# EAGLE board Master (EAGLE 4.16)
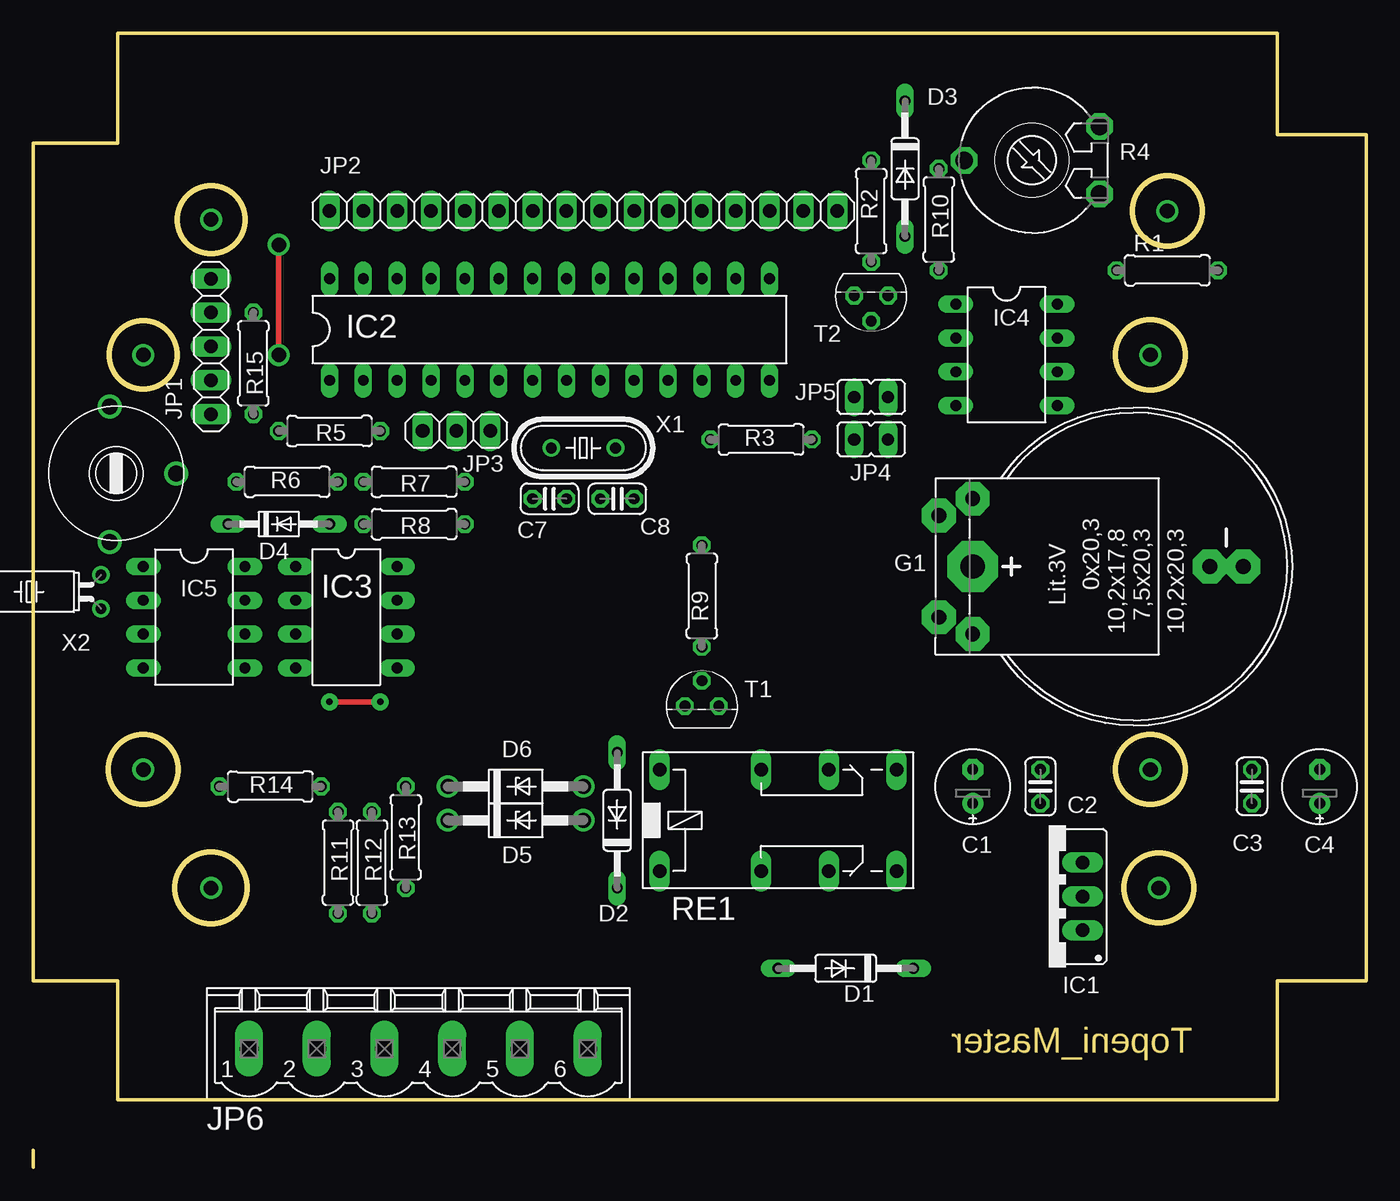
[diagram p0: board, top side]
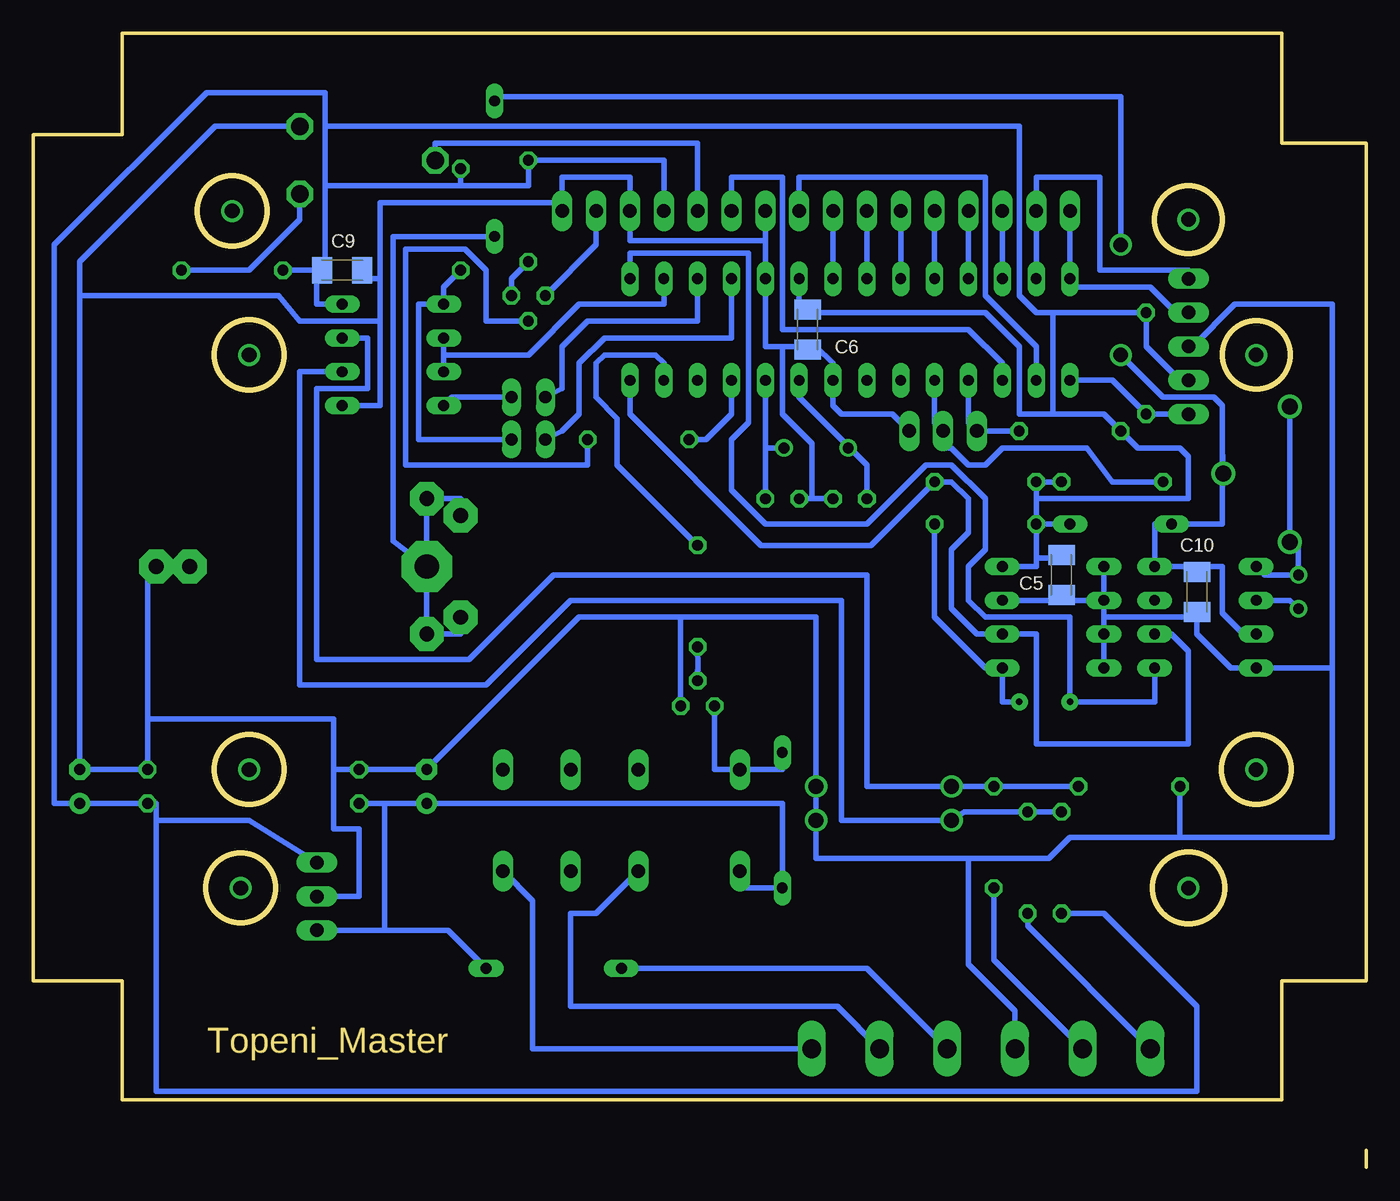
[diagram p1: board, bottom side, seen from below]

Size 100.01 x 85.09 mm. Coordinates in mm from the lower left corner, seen from the top.
Outline: 77 segments
Outline: circle at 13.34,71.12 radius 2.54
Outline: circle at 8.26,60.96 radius 2.54
Outline: circle at 8.26,29.84 radius 2.62
Outline: circle at 13.34,20.95 radius 2.69
Outline: circle at 85.09,71.75 radius 2.62
Outline: circle at 83.82,60.96 radius 2.62
Outline: circle at 83.82,29.84 radius 2.62
Outline: circle at 84.45,20.95 radius 2.62
Copper layers (1*16): Top 0.035mm / dielectric 1.5mm / Bottom 0.035mm
Design rules "default": minimum track width 10mil, minimum drill 19mil, track to track 8mil, track to pad 8mil, pad to pad 8mil, via to via 8mil, smd to smd 8mil, copper to edge 40mil, drill to drill 8mil, minimum pad ring 10mil, minimum via ring 8mil, stop-mask expansion 4mil, vias tented up to drill 0mil, thermal gap 10mil

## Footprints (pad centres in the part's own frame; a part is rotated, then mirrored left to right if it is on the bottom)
E2,5-6E = drill 0.813 pad 1.575 round: + -1.27,0 | drill 0.813 pad 1.575 octagon: - 1.27,0
C025-024X044 = drill 0.813 octagon: 1 -1.27,0; 2 1.27,0
C1206K = smd 1.5 x 2: 1 -1.5,0; 2 1.5,0
CAP-GM = drill 1.2 round: P$1 -5,0 | drill 1.2 pad 1.676 round: P$2 5.16,0; P$3 0,5
DO35-10 = drill 0.813 long: A 5.08,0; C -5.08,0
DO34-7 = drill 0.813 long: A 3.81,0; C -3.81,0
DO41Z10 = drill 1.118 round: A 5.08,0; C -5.08,0
B2430UNI = drill 1.118 pad 2.54 octagon: + 3.81,14.605; +@1 -3.81,14.605; +@2 -5.08,12.065; +@3 5.08,12.065; - 0,-5.715; -@1 0,-8.255 | drill 1.803 pad 3.81 octagon: +@4 0,12.065
78XXS = drill 1.016 long: GND 0,-2.54; IN -2.54,-2.54; OUT 2.54,-2.54
DIL28-3 = drill 0.813 long: 1 -16.51,-3.81; 2 -13.97,-3.81; 3 -11.43,-3.81; 4 -8.89,-3.81; 5 -6.35,-3.81; 6 -3.81,-3.81; 7 -1.27,-3.81; 8 1.27,-3.81; 9 3.81,-3.81; 10 6.35,-3.81; 11 8.89,-3.81; 12 11.43,-3.81; 13 13.97,-3.81; 14 16.51,-3.81; 15 16.51,3.81; 16 13.97,3.81; 17 11.43,3.81; 18 8.89,3.81; 19 6.35,3.81; 20 3.81,3.81; 21 1.27,3.81; 22 -1.27,3.81; 23 -3.81,3.81; 24 -6.35,3.81; 25 -8.89,3.81; 26 -11.43,3.81; 27 -13.97,3.81; 28 -16.51,3.81
DIL8 = drill 0.813 long: 1 -3.81,-3.81; 2 -1.27,-3.81; 3 1.27,-3.81; 4 3.81,-3.81; 5 3.81,3.81; 6 1.27,3.81; 7 -1.27,3.81; 8 -3.81,3.81
DIL08 = drill 0.813 long: 1 -3.81,-3.81; 2 -1.27,-3.81; 3 1.27,-3.81; 4 3.81,-3.81; 5 3.81,3.81; 6 1.27,3.81; 7 -1.27,3.81; 8 -3.81,3.81
1X05 = drill 1.016 long: 1 -5.08,0; 2 -2.54,0; 3 0,0; 4 2.54,0; 5 5.08,0
1X16 = drill 1.016 long: 1 -19.05,0; 2 -16.51,0; 3 -13.97,0; 4 -11.43,0; 5 -8.89,0; 6 -6.35,0; 7 -3.81,0; 8 -1.27,0; 9 1.27,0; 10 3.81,0; 11 6.35,0; 12 8.89,0; 13 11.43,0; 14 13.97,0; 15 16.51,0; 16 19.05,0
1X03 = drill 1.016 long: 1 -2.54,0; 2 0,0; 3 2.54,0
JP1 = drill 0.914 long: 1 0,-1.27; 2 0,1.27
MSTBV6 = drill 1.397 long: 1 -12.7,0; 2 -7.62,0; 3 -2.54,0; 4 2.54,0; 5 7.62,0; 6 12.7,0
0207/7 = drill 0.813 octagon: 1 -3.81,0; 2 3.81,0
LI10 = drill 1.321 octagon: A -2.54,-5.08; E 2.54,-5.08; S 0,5.08
351 = drill 1.016 long: 1 -3.81,-3.81; 16 -3.81,3.81; O1 8.89,-3.81; O2 8.89,3.81; P1 3.81,-3.81; P2 3.81,3.81; S1 13.97,-3.81; S2 13.97,3.81
TO92 = drill 0.813 octagon: 1 1.27,0; 2 0,1.905; 3 -1.27,0
HC49/S = drill 0.813 round: 1 -2.413,0; 2 2.413,0
TC38H = drill 0.813 round: 1 -1.27,0; 2 1.27,0

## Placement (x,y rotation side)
C1  [E2,5-6E]  70.48,28.57 90 top
C2  [C025-024X044]  75.56,28.57 90 top
C3  [C025-024X044]  91.44,28.57 90 top
C4  [E2,5-6E]  96.52,28.57 90 top
C5  [C1206K]  22.86,44.45 90 bottom
C6  [C1206K]  41.91,62.87 270 bottom
C7  [C025-024X044]  38.73,50.17 180 top
C8  [C025-024X044]  43.81,50.17 0 top
C9  [C1206K]  76.83,67.31 180 bottom
C10  [C1206K]  12.7,43.18 90 bottom
C11  [CAP-GM]  5.71,52.07 270 top
D1  [DO35-10]  60.96,14.92 180 top
D2  [DO35-10]  43.81,26.04 90 top
D3  [DO35-10]  65.41,74.93 270 top
D4  [DO34-7]  18.41,48.26 0 top
D5  [DO41Z10]  36.2,26.04 0 top
D6  [DO41Z10]  36.2,28.57 0 top
G1  B2430UNI  [B2430UNI]  82.55,45.09 90 top
IC1  [78XXS]  76.2,20.32 90 top
IC2  PIC16F873A  [DIL28-3]  38.73,62.87 0 top
IC3  [DIL8]  23.5,41.28 270 top
IC4  [DIL08]  73.03,60.96 270 top
IC5  [DIL08]  12.06,41.28 270 top
JP1  [1X05]  13.34,61.6 90 top
JP2  [1X16]  41.27,71.75 0 top
JP3  [1X03]  31.75,55.25 180 top
JP4  [JP1]  62.87,54.61 270 top
JP5  [JP1]  62.87,57.79 270 top
JP6  [MSTBV6]  28.89,8.89 0 top
R1  [0207/7]  85.09,67.31 0 top
R2  [0207/7]  62.87,71.75 270 top
R3  [0207/7]  54.61,54.61 0 top
R4  [LI10]  74.93,75.56 90 top
R5  [0207/7]  22.23,55.25 180 top
R6  [0207/7]  19.05,51.44 0 top
R7  [0207/7]  28.57,51.44 180 top
R8  [0207/7]  28.57,48.26 180 top
R9  [0207/7]  50.16,42.86 90 top
R10  [0207/7]  67.94,71.12 270 top
R11  [0207/7]  22.86,22.86 270 top
R12  [0207/7]  25.4,22.86 270 top
R13  [0207/7]  27.94,24.77 270 top
R14  [0207/7]  17.78,28.57 0 top
R15  [0207/7]  16.51,60.33 90 top
RE1  [351]  50.8,26.04 0 top
T1  [TO92]  50.16,34.61 0 top
T2  [TO92]  62.87,65.41 180 top
U$1  [ARROW-->]  100.01,1.27 0 top
U$2  [ARROW<--]  0,1.27 0 top
X1  [HC49/S]  41.27,53.98 180 top
X2  [TC38H]  5.08,43.18 90 top

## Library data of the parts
C1-C10 R1-R3 R5-R15 = rcl
C11 = #hacesoft
D1-D6 = diode
G1 = battery
IC1 = v-reg
IC2 IC3 = microchip
IC4 IC5 = ic-package
JP1-JP3 = pinhead
JP4 JP5 = jumper
JP6 = con-phoenix-508
R4 = pot
RE1 = relay
T1 T2 = transistor-npn
U$1 U$2 = marks
X1 X2 = crystal

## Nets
+12V: C1.+ C2.1 D1.C D2.C IC1.IN RE1.1
CLOCK: IC2.14 IC3.6 IC5.6 R7.1
D0: IC2.21 JP2.8
D1: IC2.22 JP2.7
D2: IC2.23 JP2.6
D3: IC2.24 JP2.5
D4: IC2.25 JP2.4
D5: IC2.26 JP2.3
D6: IC2.27 JP1.5 JP2.2
D7: IC2.28 JP1.4 JP2.1
DATA: IC2.15 IC3.5 IC5.5 R8.1
EN: IC2.2 JP2.9
N$1: JP2.12 R4.S
N$2: D1.A JP6.4
N$3: IC2.4 JP3.3 R5.1
N$4: IC2.5 JP3.2 R6.1
N$5: JP6.6 RE1.S1
N$6: D3.A G1.+ G1.+@1 G1.+@2 G1.+@3 G1.+@4
N$7: C7.2 IC2.9 X1.2
N$8: C8.2 IC2.10 X1.1
N$9: C10.2 C11.P$3 D3.C D4.C IC5.3 IC5.8
N$10: JP6.5 RE1.P1
N$11: IC2.1 JP1.1 R15.1
N$12: D2.A RE1.16 T1.3
N$13: IC4.1 JP4.2 R10.2
N$14: IC4.4 JP5.2
N$15: R1.2 R4.A
N$16: D5.C IC4.6 R11.1 R12.1
N$17: D6.C IC4.7 R13.1 R14.2
N$18: R2.2 T2.3
N$19: IC2.18 JP4.1
N$20: IC2.17 JP5.1
N$23: R3.2 T2.2
N$28: IC5.2 X2.1
N$29: C11.P$1 C11.P$2 IC5.1 X2.2
N$30: JP2.15 T2.1
N$39: JP6.2 R13.2
N$40: JP6.1 R12.2
PODSVETLENI: IC2.11 R3.1
RELE: R9.1 T1.2
RELE1: IC2.13 R9.2
RS: IC2.3 JP2.11
SMER: IC2.16 IC4.2 IC4.3
VDD: C3.1 C4.+ C5.2 C6.1 C9.2 D4.A IC1.OUT IC2.20 IC3.8 IC4.8 JP1.2 JP2.13 R1.1 R2.1 R5.2 R6.2 R7.2 R8.2 R10.1 R11.2 R15.2
VSS: C1.- C2.2 C3.2 C4.- C5.1 C6.2 C7.1 C8.1 C9.1 C10.1 D5.A D6.A G1.- G1.-@1 IC1.GND IC2.8 IC2.19 IC3.1 IC3.2 IC3.3 IC3.4 IC3.7 IC4.5 IC5.4 JP1.3 JP2.10 JP2.14 JP2.16 JP3.1 JP6.3 R4.E R14.1 T1.1

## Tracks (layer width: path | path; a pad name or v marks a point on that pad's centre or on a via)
+12V
  Bottom 0.4: D1.C 68.9,17.78 73.66,17.78 | 73.66,17.78 IC1.IN | 73.66,27.3 73.66,17.78
  Bottom 0.406: C2.1 73.66,27.3 C1.+ 43.81,27.3 D2.C 46.99,20.95 RE1.1
CLOCK
  Bottom 0.406: IC2.14 55.24,56.52 45.4,46.67 37.15,46.67 R7.1 31.11,51.44 29.84,50.17 29.84,47.62 31.11,46.36 31.11,41.91 29.21,40.01 IC3.6 24.77,40.01 24.77,31.75 13.34,31.75 13.34,38.74 14.61,40.01 IC5.6
D0
  Bottom 0.406: IC2.21 JP2.8
D1
  Bottom 0.406: IC2.22 JP2.7
D2
  Bottom 0.406: IC2.23 JP2.6
D3
  Bottom 0.406: IC2.24 JP2.5
D4
  Bottom 0.406: IC2.25 JP2.4
D5
  Bottom 0.406: IC2.26 JP2.3
D6
  Bottom 0.406: IC2.27 JP2.2 24.77,74.3 20,74.3 20,67.31 13.34,67.31 JP1.5
D7
  Bottom 0.4: JP1.4 14.29,64.14 16.19,66.04
  Bottom 0.406: JP2.1 IC2.28 22.23,66.04 16.19,66.04
DATA  (via drill 0.5 pad 1.27)
  Top 0.406: v22.23,34.93 v26.04,34.93
  Bottom 0.406: v26.04,34.93 27.3,34.93 IC3.5 28.57,37.47 32.38,41.28 R8.1 | IC5.5 15.88,34.93 v22.23,34.93 22.23,41.28 28.57,41.28 29.84,42.55 29.84,45.09 28.57,46.36 28.57,50.17 31.11,52.71 33.02,52.71 37.47,48.26 45.09,48.26 47.62,50.8 47.62,54.61 46.35,55.88 46.35,68.58 55.24,68.58 IC2.15
EN
  Bottom 0.406: IC2.2 24.77,61.6 28.57,65.41 28.57,74.3 42.55,74.3 JP2.9
N$1
  Bottom 0.406: R4.S 69.85,76.83 50.16,76.83 JP2.12
N$2
  Bottom 0.4: JP6.4 37.47,14.92 D1.A
N$3
  Bottom 0.406: R5.1 JP3.3 29.84,55.88 IC2.4
N$4
  Bottom 0.406: R6.1 19.05,51.44 20.95,53.98 27.3,53.98 28.57,52.71 29.84,52.71 31.11,53.98 31.75,53.98 JP3.2 32.38,55.88 IC2.5
N$5
  Bottom 0.4: RE1.S1 62.55,20 62.55,8.89 JP6.6
N$6
  Bottom 0.406: D3.A 73.03,69.85 73.03,46.99 G1.+@4 | G1.+@4 G1.+@3 67.94,50.17 G1.+ | G1.+@4 G1.+@2 67.94,40.01 G1.+@1
N$7
  Bottom 0.406: C7.2 37.47,52.71 38.73,53.98 | 38.73,53.98 42.55,57.79 IC2.9 | 38.73,53.98 X1.2
N$8
  Bottom 0.406: C8.2 45.09,53.98 | 45.09,53.98 IC2.10 | 45.09,53.98 X1.1
N$9  (via drill 1.1)
  Top 0.406: v18.41,60.96 v18.41,69.21
  Bottom 0.254: C10.2 13.34,44.45 13.34,45.09 | C11.P$3 10.79,54.61 10.79,53.98
  Bottom 0.4: IC5.3 9.21,40.01 10.79,41.59
  Bottom 0.406: D3.C 65.41,80.33 18.41,80.33 v18.41,69.21 | v18.41,60.96 15.24,57.79 11.43,57.79 10.79,57.15 10.79,54.61 10.79,53.34 | 10.79,53.34 10.79,48.26 D4.C 15.88,48.26 IC5.8 13.34,45.09 10.79,45.09 10.79,41.59 | 10.79,53.34 C11.P$3 10.79,53.98
N$10
  Bottom 0.4: RE1.P1 57.78,19.05 59.69,19.05 59.69,12.06 39.69,12.06 JP6.5
N$11
  Bottom 0.406: IC2.1 19.05,59.05 R15.1 JP1.1
N$12
  Bottom 0.406: D2.A 43.81,29.84 RE1.16 48.9,29.84 T1.3
N$13
  Bottom 0.4: 69.22,66.04 R10.2
  Bottom 0.406: JP4.2 71.12,54.61 71.12,64.77 IC4.1 69.22,66.04
N$14
  Bottom 0.406: JP5.2 68.58,57.79 IC4.4
N$15
  Bottom 0.406: R1.2 83.82,67.31 80.01,71.12 R4.A
N$16
  Bottom 0.4: 30.16,26.67 R12.1 R11.1
  Bottom 0.406: 30.16,26.67 D5.C 39.37,26.04 39.37,42.55 59.69,42.55 66.04,36.2 80.01,36.2 80.01,59.69 IC4.6
N$17
  Bottom 0.4: R14.2 R13.1 D6.C
  Bottom 0.406: D6.C 37.47,28.57 37.47,44.45 60.96,44.45 67.31,38.1 78.74,38.1 78.74,58.42 74.93,58.42 74.93,62.23 IC4.7
N$18
  Bottom 0.406: T2.3 64.14,66.67 R2.2
N$19
  Bottom 0.406: IC2.18 47.62,62.23 57.15,62.23 59.05,60.33 59.05,56.52 60.33,55.25 JP4.1
N$20
  Bottom 0.406: IC2.17 50.16,63.5 58.42,63.5 60.33,61.6 60.33,58.42 JP5.1
N$23
  Bottom 0.406: T2.2 66.04,63.5 66.04,67.31 67.63,68.9 72.07,68.9 72.07,52.71 58.42,52.71 R3.2
N$28
  Bottom 0.406: X2.1 5.71,42.55 IC5.2
N$29
  Bottom 0.254: C11.P$2 5.71,46.99
  Bottom 0.406: IC5.1 7.62,44.45 X2.2 5.08,46.99 5.67,47.06 5.59,47.02 5.71,46.99 C11.P$1 5.71,57.15
N$30
  Bottom 0.406: T2.1 57.78,69.21 JP2.15
N$39
  Bottom 0.4: JP6.2 27.94,15.56 R13.2
N$40
  Bottom 0.4: JP6.1 25.4,18.1 R12.2
PODSVETLENI
  Bottom 0.406: IC2.11 47.62,56.52 49.53,54.61 R3.1
RELE
  Bottom 0.406: 50.15,37.5 50.16,37.21 | 50.15,37.5 R9.1 | T1.2 50.16,36.2 50.15,37.5
RELE1
  Bottom 0.406: IC2.13 52.7,60.33 53.34,60.96 57.15,60.96 57.78,60.33 57.78,57.79 56.2,56.2 56.2,52.71 R9.2
RS
  Bottom 0.406: IC2.3 27.3,60.33 29.84,62.87 43.81,62.87 43.81,74.3 47.62,74.3 JP2.11
S$1  (via drill 1.1)
  other vias: 13.34,20.95
S$12  (via drill 1.1)
  other vias: 8.26,29.84
S$14  (via drill 1.1)
  other vias: 8.26,60.96
S$19  (via drill 1.1)
  other vias: 13.34,71.12
S$20  (via drill 1.1)
  other vias: 85.09,71.75
S$23  (via drill 1.1)
  other vias: 83.82,60.96
S$24  (via drill 1.1)
  other vias: 83.82,29.84
S$25  (via drill 1.1)
  other vias: 84.45,20.95
SMER
  Bottom 0.406: 69.22,60.96 IC4.3 | 69.22,60.96 IC4.2 | IC2.16 52.7,64.77 59.05,64.77 62.87,60.96 69.22,60.96
VDD
  Bottom 0.254: 23.5,45.72 C5.2 | C6.1 41.27,64.77 41.91,64.14 | C9.2 78.11,67.31 78.74,67.31
  Bottom 0.4: 12.7,5.71 12.7,12.06 19.68,19.05 R11.2 | 67.94,73.66 R10.1
  Bottom 0.406: 22.86,45.72 23.5,45.72 24.77,45.72 | IC3.8 24.77,45.09 24.77,45.72 | R6.2 R7.2 24.77,50.17 | R8.2 24.77,45.72 | R8.2 D4.A | 24.77,50.17 R8.2 | 24.77,50.17 13.34,50.17 13.34,53.34 13.97,53.98 17.14,53.98 R5.2 19.68,56.52 23.5,56.52 | IC2.20 42.55,64.14 41.91,64.14 28.57,64.14 26.04,61.6 26.04,56.52 23.5,56.52 | 23.5,64.14 23.5,56.52 | 23.5,64.14 R15.2 16.51,61.6 13.97,59.05 JP1.2 | 23.5,64.14 24.77,64.14 26.04,65.41 26.04,78.1 35.88,78.1 | JP2.13 52.7,75.56 R2.1 62.87,73.66 67.94,73.66 78.11,73.66 | 35.88,78.1 38.73,78.1 | 78.11,73.66 78.11,67.31 78.11,66.67 | 78.11,78.1 78.11,73.66 | 78.11,78.1 35.88,78.1 | 78.11,78.1 78.11,80.64 87,80.64 98.42,69.21 98.42,27.3 | C3.1 C4.+ 98.42,27.3 | IC1.OUT 83.82,26.04 90.81,26.04 | 98.42,27.3 90.81,27.3 90.81,26.04 | 90.81,26.04 90.81,5.71 12.7,5.71 | IC4.8 78.74,64.77 78.74,67.31 | 78.74,67.31 78.74,66.67 | 78.74,67.31 R1.1
VSS
  Bottom 0.254: C6.2 42.55,60.96 42.55,61.6 | 75.56,67.31 C9.1 75.25,66.67 74.3,66.67 | 22.23,43.18 C5.1 23.5,43.18 23.5,42.55 | C10.1 13.34,41.91 13.34,41.28
  Bottom 0.4: JP6.3 26.35,11.75 29.84,15.24 29.84,23.18 | 12.06,61.6 JP1.3 13.02,61.6 9.84,64.77 | 29.84,23.18 41.27,23.18 | 29.84,23.18 23.81,23.18 22.23,24.77 | 13.97,24.77 R14.1
  Bottom 0.406: JP3.1 35.56,56.52 39.37,56.52 40.01,57.15 IC2.8 40.01,60.33 41.27,61.6 42.55,61.6 43.81,61.6 | 41.59,50.17 C8.1 | 41.59,50.17 C7.1 | 41.59,50.17 41.59,54.29 43.81,56.52 43.81,61.6 | 43.81,61.6 45.09,61.6 IC2.19 | IC2.19 45.09,64.14 | 45.09,69.53 IC2.19 | 45.09,69.53 JP2.10 | 45.09,69.53 55.24,69.53 JP2.14 55.24,74.3 60.33,74.3 60.33,72.39 | 60.33,72.39 JP2.16 | 74.93,66.67 74.3,66.67 73.98,66.67 | 60.33,72.39 73.98,72.39 73.98,66.67 | IC4.5 73.98,57.15 73.98,63.5 | 73.98,63.5 73.98,66.67 | R4.E 86.36,78.1 96.52,67.94 96.52,65.41 | 73.98,63.5 80.01,63.5 81.6,65.41 96.52,65.41 | 96.52,65.41 C4.- C3.2 91.44,33.66 | G1.- G1.-@1 91.44,45.09 91.44,33.66 | IC1.GND 75.56,20.32 75.56,25.4 77.47,25.4 77.47,29.84 | 91.44,33.66 77.47,33.66 77.47,29.84 | 77.47,29.84 C2.2 C1.- 59.05,41.28 51.44,41.28 | IC3.7 23.5,42.55 IC3.2 | IC3.4 IC3.3 19.68,41.28 | IC3.2 IC3.1 | 51.44,41.28 T1.1 | 51.44,41.28 41.27,41.28 D6.A | 19.68,41.28 IC3.2 | 19.68,41.28 13.34,41.28 12.7,41.28 12.7,40.01 10.16,37.47 IC5.4 2.54,37.47 | D6.A D5.A | D6.A 41.27,30.48 | 41.27,23.18 D6.A | JP1.3 12.7,61.6 | 9.84,64.77 2.54,64.77 2.54,37.47 | 2.54,37.47 3.81,37.47 | 2.54,37.47 2.54,24.77 13.97,24.77 22.23,24.77

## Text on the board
Dimension: Topeni_Master
Measures: 100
